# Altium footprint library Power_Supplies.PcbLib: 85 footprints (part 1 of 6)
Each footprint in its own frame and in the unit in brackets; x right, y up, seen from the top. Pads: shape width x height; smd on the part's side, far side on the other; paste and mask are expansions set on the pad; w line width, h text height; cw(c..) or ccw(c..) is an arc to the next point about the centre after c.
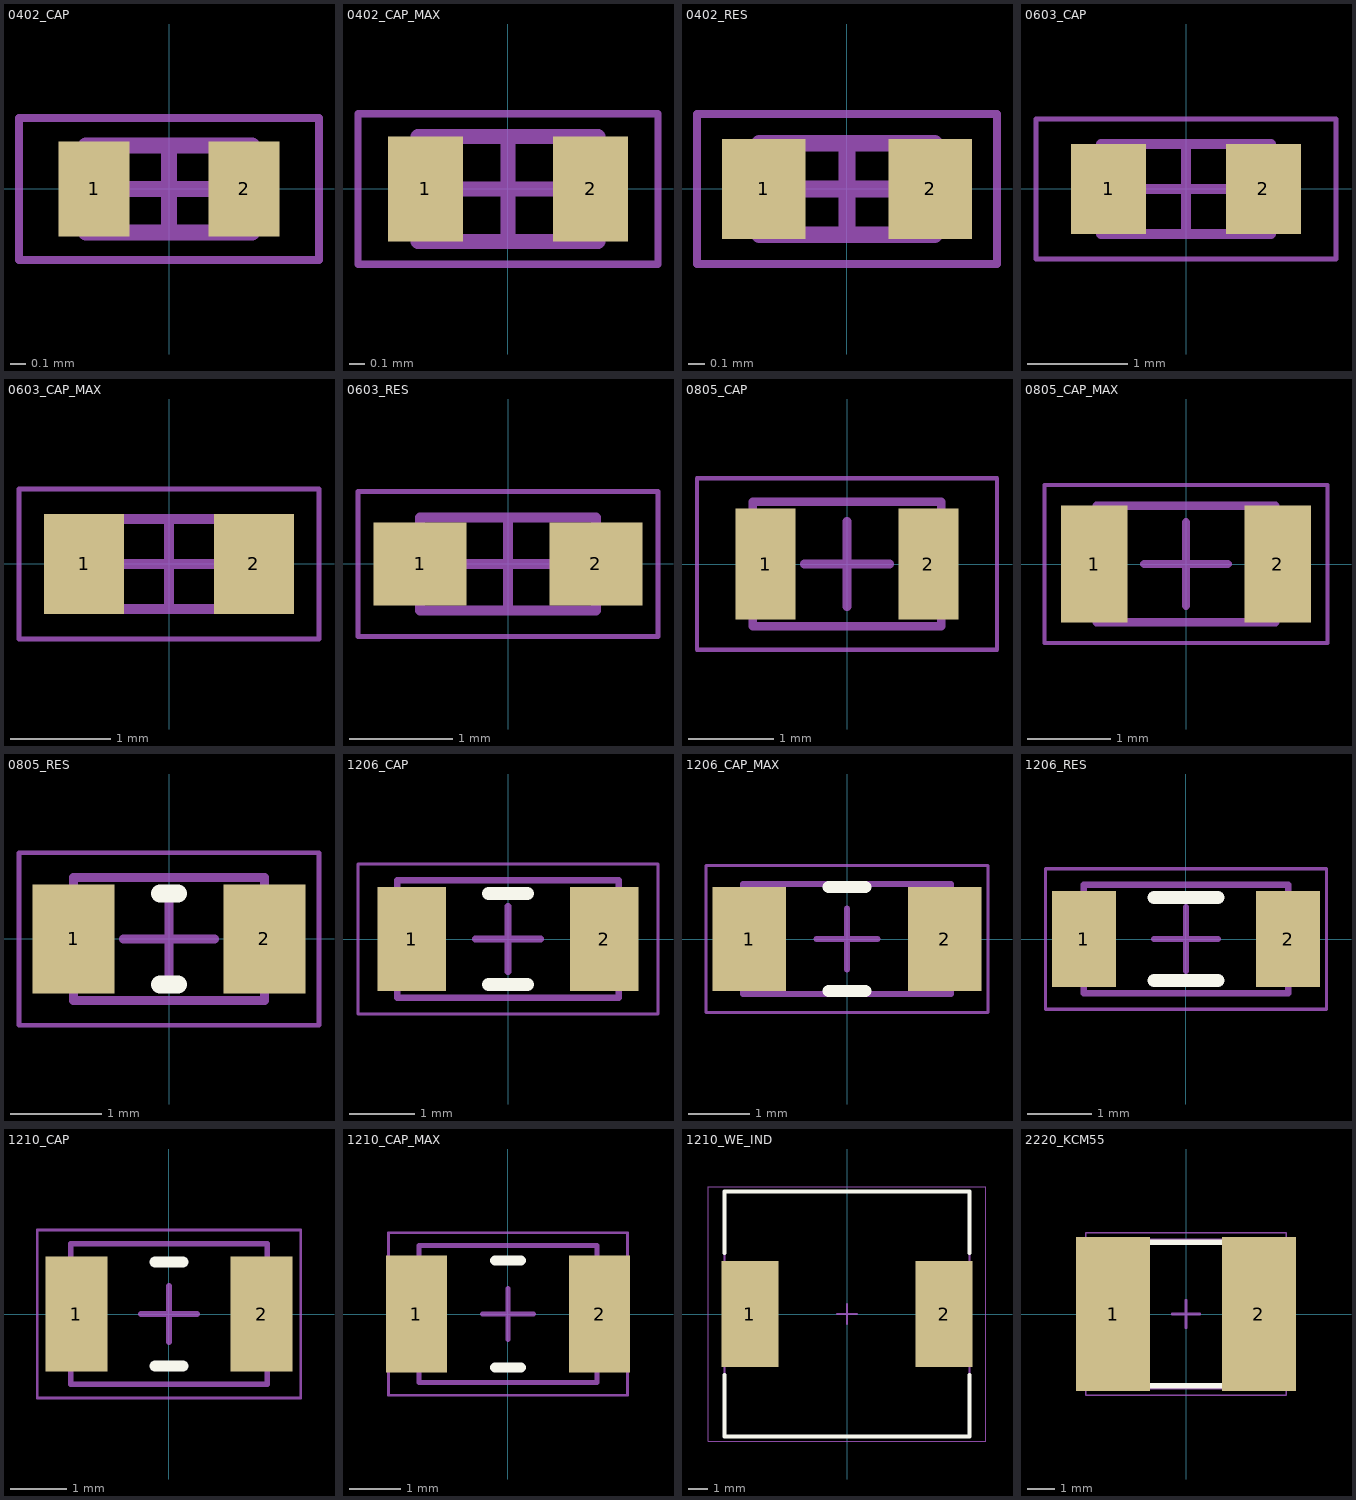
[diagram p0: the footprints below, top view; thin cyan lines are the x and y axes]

## 0402_CAP [mm] "0402, MLCC, GRT Series, middle dimensions from reflow soldering, +/-0.15/+/-0.20 tolerances"
height 0.55
pads (2):
  rect 0.45x0.6 smd: 1(-0.475,0) 2(0.475,0)
Mechanical 13:
  lines w0.1: -0.525,-0.275 -0.525,0.275 0.525,0.275 0.525,-0.275 -0.525,-0.275
Mechanical 15:
  lines w0.05: -0.95,-0.45 -0.95,0.45 0.95,0.45 0.95,-0.45 -0.95,-0.45
  lines w0.1: -0.275,0 0.275,0 ; 0,-0.275 0,0.275
3D body "0402_CAP.step": height 0.55, standoff 0, extent -0.525,-0.275 0.525,0.275

## 0402_CAP_MAX [mm] "0402, MLCC, GCM Series, max dimensions from reflow soldering"
height 0.7
pads (2):
  rect 0.5x0.7 smd: 1(-0.55,0) 2(0.55,0)
Mechanical 13:
  lines w0.1: -0.6,-0.35 -0.6,0.35 0.6,0.35 0.6,-0.35 -0.6,-0.35
Mechanical 15:
  lines w0.05: -1,-0.5 -1,0.5 1,0.5 1,-0.5 -1,-0.5
  lines w0.1: -0.35,0 0.35,0 ; 0,-0.35 0,0.35
3D body "0402_CAP_MAX_2.step": height 0.7, standoff 0, extent -0.6,-0.35 0.6,0.35

## 0402_RES [mm] "0402, Reflow, YAGEO"
height 0.4
pads (2):
  rect 0.5x0.6 smd: 1(-0.5,0) 2(0.5,0)
Mechanical 13:
  lines w0.1: -0.525,-0.275 -0.525,0.275 0.525,0.275 0.525,-0.275 -0.525,-0.275
Mechanical 15:
  lines w0.05: -0.9,-0.45 -0.9,0.45 0.9,0.45 0.9,-0.45 -0.9,-0.45
  lines w0.1: -0.275,0 0.275,0 ; 0,-0.275 0,0.275
3D body "0402_RES.step": height 0.4, standoff 0, extent -0.525,-0.275 0.525,0.275

## 0603_CAP [mm] "0603, MLCC, GRT Series, middle dimensions from reflow soldering, +/-0.15/+/-0.20 tolerances"
height 0.9
pads (2):
  rect 0.75x0.9 smd: 1(-0.775,0) 2(0.775,0)
Mechanical 13:
  lines w0.1: -0.85,-0.45 0.85,-0.45 0.85,0.45 -0.85,0.45 -0.85,-0.45
Mechanical 15:
  lines w0.05: -1.5,-0.7 1.5,-0.7 1.5,0.7 -1.5,0.7 -1.5,-0.7
  lines w0.1: -0.45,0 0.45,0 ; 0,-0.45 0,0.45
3D body "0603_CAP.step": height 0.9, standoff 0, extent -0.85,-0.45 0.85,0.45

## 0603_CAP_MAX [mm] "0603, MLCC, GCM Series, max dimensions from reflow soldering"
height 0.9
pads (2):
  rect 0.8x1 smd: 1(-0.85,0) 2(0.85,0)
Mechanical 13:
  lines w0.1: -0.85,-0.45 0.85,-0.45 0.85,0.45 -0.85,0.45 -0.85,-0.45
Mechanical 15:
  lines w0.05: -1.5,-0.75 1.5,-0.75 1.5,0.75 -1.5,0.75 -1.5,-0.75
  lines w0.1: -0.45,0 0.45,0 ; 0,-0.45 0,0.45
3D body "0603_CAP_MAX.step": height 0.9, standoff 0, extent -0.85,-0.45 0.85,0.45

## 0603_RES [mm] "Chip Resistor, 2-Leads, Body 1.60x0.80mm, IPC Medium Density"
height 0.55
pads (2):
  rect 0.9x0.8 smd: 1(-0.85,0) 2(0.85,0)
Mechanical 13:
  lines w0.1: -0.85,-0.45 0.85,-0.45 0.85,0.45 -0.85,0.45 -0.85,-0.45
Mechanical 15:
  lines w0.05: -1.45,-0.7 1.45,-0.7 1.45,0.7 -1.45,0.7 -1.45,-0.7
  lines w0.1: -0.45,0 0.45,0 ; 0,-0.45 0,0.45
3D body "0603_RES.step": height 0.55, standoff 0, extent -0.85,-0.45 0.85,0.45

## 0805_CAP [mm] "0805, MLCC, GRT Series, middle dimensions from reflow soldering, +/-0.20 tolerances"
height 1.45
pads (2):
  rect 0.7x1.3 smd: 1(-0.95,0) 2(0.95,0)
Mechanical 13:
  lines w0.1: -1.1,-0.725 -1.1,0.725 1.1,0.725 1.1,-0.725 -1.1,-0.725
Mechanical 15:
  lines w0.05: -1.75,-1 -1.75,1 1.75,1 1.75,-1 -1.75,-1
  lines w0.1: -0.5,0 0.5,0 ; 0,-0.5 0,0.5
3D body "0805_CAP.step": height 1.45, standoff 0, extent -1.1,-0.725 1.1,0.725

## 0805_CAP_MAX [mm] "0805, MLCC, GCM Series, max dimensions from reflow soldering"
height 1.4
pads (2):
  rect 0.8x1.4 smd: 1(-1.1,0) 2(1.1,0)
Mechanical 13:
  lines w0.1: -1.075,-0.7 -1.075,0.7 1.075,0.7 1.075,-0.7 -1.075,-0.7
Mechanical 15:
  lines w0.05: -1.7,-0.95 -1.7,0.95 1.7,0.95 1.7,-0.95 -1.7,-0.95
  lines w0.1: -0.5,0 0.5,0 ; 0,-0.5 0,0.5
3D body "0805_CAP_MAX.step": height 1.4, standoff 0, extent -1.075,-0.7 1.075,0.7

## 0805_RES [mm] "0805, Reflow, YAGEO"
height 0.6
pads (2):
  rect 0.9x1.2 smd: 1(-1.05,0) 2(1.05,0)
Top Overlay:
  lines w0.2: -0.1,-0.5 0.1,-0.5 ; -0.1,0.5 0.1,0.5
Mechanical 13:
  lines w0.1: -1.05,-0.675 -1.05,0.675 1.05,0.675 1.05,-0.675 -1.05,-0.675
Mechanical 15:
  lines w0.05: -1.65,-0.95 -1.65,0.95 1.65,0.95 1.65,-0.95 -1.65,-0.95
  lines w0.1: -0.5,0 0.5,0 ; 0,-0.5 0,0.5
3D body "0805_RES.step": height 0.6, standoff 0, extent -1.05,-0.675 1.05,0.675

## 1206_CAP [mm] "1206_CAP, MLCC, GRT Series, middle dimensions from reflow soldering, +/-0.20 tolerances"
height 1.88
pads (2):
  rect 1.05x1.6 smd: 1(-1.475,0) 2(1.475,0)
Top Overlay:
  lines w0.2: -0.3,-0.7 0.3,-0.7 ; -0.3,0.7 0.3,0.7
Mechanical 13:
  lines w0.1: -1.7,-0.9 1.7,-0.9 1.7,0.9 -1.7,0.9 -1.7,-0.9
Mechanical 15:
  lines w0.05: -2.3,-1.15 2.3,-1.15 2.3,1.15 -2.3,1.15 -2.3,-1.15
  lines w0.1: -0.5,0 0.5,0 ; 0,-0.5 0,0.5
3D body "1206_CAP.step": height 1.8, standoff 0, extent -1.7,-0.9 1.7,0.9

## 1206_CAP_MAX [mm] "1206, MLCC, GCM Series, max dimensions from reflow soldering"
height 1.8
pads (2):
  rect 1.2x1.7 smd: 1(-1.6,0) 2(1.6,0)
Top Overlay:
  lines w0.2: -0.3,-0.85 0.3,-0.85 ; -0.3,0.85 0.3,0.85
Mechanical 13:
  lines w0.1: -1.7,-0.9 1.7,-0.9 1.7,0.9 -1.7,0.9 -1.7,-0.9
Mechanical 15:
  lines w0.05: -2.3,-1.2 2.3,-1.2 2.3,1.2 -2.3,1.2 -2.3,-1.2
  lines w0.1: -0.5,0 0.5,0 ; 0,-0.5 0,0.5
3D body "1206_CAP_MAX.step": height 1.8, standoff 0, extent -1.7,-0.9 1.7,0.9

## 1206_RES [mm] "1206, Reflow, YAGEO"
height 0.65
pads (2):
  rect 1x1.5 smd: 1(-1.6,0) 2(1.6,0)
Top Overlay:
  lines w0.2: -0.5,-0.65 0.5,-0.65 ; -0.5,0.65 0.5,0.65
Mechanical 13:
  lines w0.1: -1.6,-0.85 -1.6,0.85 1.6,0.85 1.6,-0.85 -1.6,-0.85
Mechanical 15:
  lines w0.05: -2.2,-1.1 -2.2,1.1 2.2,1.1 2.2,-1.1 -2.2,-1.1
  lines w0.1: -0.5,0 0.5,0 ; 0,-0.5 0,0.5
3D body "1206_RES.step": height 0.65, standoff 0, extent -1.6,-0.85 1.6,0.85

## 1210_CAP [mm] "1210_CAP, MLCC, GRT Series, middle dimensions from reflow soldering, +/-0.20 tolerances"
height 2.7
pads (2):
  rect 1.1x2.05 smd: 1(-1.65,0) 2(1.65,0)
Top Overlay:
  lines w0.2: -0.25,-0.925 0.25,-0.925 ; -0.25,0.925 0.25,0.925
Mechanical 13:
  lines w0.1: -1.75,-1.25 1.75,-1.25 1.75,1.25 -1.75,1.25 -1.75,-1.25
Mechanical 15:
  lines w0.05: -2.35,-1.5 2.35,-1.5 2.35,1.5 -2.35,1.5 -2.35,-1.5
  lines w0.1: -0.5,0 0.5,0 ; 0,-0.5 0,0.5
3D body "1210_CAP.step": height 2.7, standoff 0, extent -1.75,-1.25 1.75,1.25

## 1210_CAP_MAX [mm] "1210, MLCC, GCM Series, max dimensions from reflow soldering"
height 2.7
pads (2):
  rect 1.2x2.3 smd: 1(-1.8,0) 2(1.8,0)
Top Overlay:
  lines w0.2: -0.25,-1.05 0.25,-1.05 ; -0.25,1.05 0.25,1.05
Mechanical 13:
  lines w0.1: -1.75,-1.35 1.75,-1.35 1.75,1.35 -1.75,1.35 -1.75,-1.35
Mechanical 15:
  lines w0.05: -2.35,-1.6 2.35,-1.6 2.35,1.6 -2.35,1.6 -2.35,-1.6
  lines w0.1: -0.5,0 0.5,0 ; 0,-0.5 0,0.5
3D body "1210_CAP_MAX.step": height 2.7, standoff 0, extent -1.75,-1.35 1.75,1.35

## 1210_WE_IND [mm] "1210_WE_IND, Wuerth Inductor"
height 10
pads (2):
  rect 2.9x5.4 smd: 1(-4.95,0) 2(4.95,0)
Top Overlay:
  lines w0.2: -6.25,-3.1 -6.25,-6.25 6.25,-6.25 6.25,-3.1 ; -6.25,3.1 -6.25,6.25 6.25,6.25 6.25,3.1
Mechanical 13:
  lines w0.1: -6.25,-6.25 6.25,-6.25 6.25,6.25 -6.25,6.25 -6.25,-6.25
Mechanical 15:
  lines w0.05: -7.075,-6.5 7.075,-6.5 7.075,6.5 -7.075,6.5 -7.075,-6.5
  lines w0.1: -0.5,0 0.5,0 ; 0,-0.5 0,0.5
3D body "STEP-WE-PD-1210-rev1(2.stp": height 9.25, standoff -0.2, extent -6,-6 6,6

## 2220_KCM55 [mm] "Chip Capacitor, 2-Leads, Body 6.1x5.3x3.7mm, IPC Medium Density"
height 6.4
pads (2):
  rect 2.7x5.6 smd: 1(-2.65,0) 2(2.65,0)
Top Overlay:
  lines w0.2: -1.45,-2.6 1.45,-2.6 ; -1.45,2.6 1.45,2.6
Mechanical 13:
  lines w0.1: -3.05,-2.7 -3.05,2.7 3.05,2.7 3.05,-2.7 -3.05,-2.7
Mechanical 15:
  lines w0.05: -3.65,-2.95 -3.65,2.95 3.65,2.95 3.65,-2.95 -3.65,-2.95
  lines w0.1: -0.5,0 0.5,0 ; 0,-0.5 0,0.5
3D body "CAPC5651X218N EIA 2220.step": height 2.18, standoff 0, extent -2.8,-2.55 2.8,2.55
3D body "CAPC5651X218N EIA 2220.step": height 4.38, standoff 2.2, extent -2.8,-2.55 2.8,2.55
